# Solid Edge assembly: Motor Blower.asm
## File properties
Author: CADCIM
Template: ansi assembly.asm
Last saved by: TIET
Revision: 5
Application: Solid Edge
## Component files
cover.par
Lower Housing.par
upper housing.par
Blower.par
motorshaft.par
Motor.par
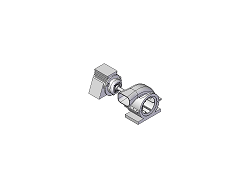
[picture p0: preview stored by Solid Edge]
